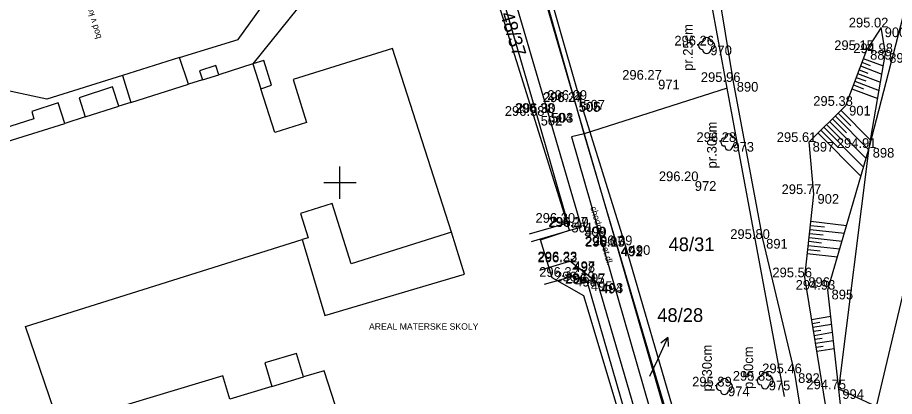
# Model space of a CAD drawing. Extents: x -599970 to -599524, y -1154772 to -1154457.
# Drawn here: x -599820 to -599765.7, y -1154663.2 to -1154639.8 of the extents above; entities that cross this region are included whole.
import ezdxf

# ---------------------------------------------------------------- set-up
doc = ezdxf.new("R2010")
doc.units = 0
for name, color, linetype in [('Z-KATASTRALNI MAPA', 7, 'Continuous'), ('Z-KRIZKY CTVERCOVE SITE', 7, 'Continuous'), ('Z-PLOT DRATENY', 7, 'Continuous'), ('Z-PLOT DREVENY', 7, 'Continuous'), ('Z-PODROBNE BODY', 7, 'Continuous'), ('Z-PODROBNE BODY-CISLO', 7, 'Continuous'), ('Z-PODROBNE BODY-VYSKA', 7, 'Continuous'), ('Z-POPISY OBJEKTU A ZPEVNENYCH PLOCH', 7, 'Continuous'), ('Z-PRUMERY KMENU STROMU', 7, 'Continuous'), ('Z-SRAFOVANI SVAHU', 7, 'Continuous'), ('Z-STROMY ZNACKY KULTUR', 7, 'Continuous'), ('Z-TERENNI HRANY PATY', 7, 'Continuous'), ('Z-ZPEVNENE PLOCHY', 7, 'Continuous')]:
    doc.layers.add(name, color=color, linetype=linetype)

msp = doc.modelspace()

# ---------------------------------------------------------------- linework, layer by layer
at = {"layer": 'Z-KATASTRALNI MAPA'}
for p, q in [((-599776.02, -1154644.14), (-599779.98, -1154622.34)), ((-599809.93, -1154642.24), (-599813.46, -1154643.34)), ((-599805.39, -1154642.63), (-599804.9, -1154644.17)), ((-599808.52, -1154643.62), (-599807.5, -1154643.3)), ((-599812.94, -1154645.02), (-599809.38, -1154643.89)), ((-599776.02, -1154644.14), (-599784.88, -1154646.97)), ((-599772.47, -1154663.26), (-599776.02, -1154644.14)), ((-599815.77, -1154645.92), (-599813.7, -1154645.26)), ((-599818.69, -1154646.84), (-599817.04, -1154646.32)), ((-599823.51, -1154648.36), (-599818.69, -1154646.84)), ((-599779.5, -1154665.17), (-599784.88, -1154646.97)), ((-599800.49, -1154651.29), (-599802.44, -1154651.91)), ((-599799.3, -1154655.03), (-599800.49, -1154651.29)), ((-599802.44, -1154651.91), (-599801.96, -1154653.41)), ((-599801.96, -1154653.41), (-599802.33, -1154653.52)), ((-599793.1, -1154653.06), (-599799.3, -1154655.03)), ((-599780.32, -1154660.95), (-599779.686, -1154659.59)), ((-599779.686, -1154659.59), (-599780.125, -1154659.938)), ((-599779.686, -1154659.59), (-599779.671, -1154660.15)), ((-599780.81, -1154661.98), (-599780.32, -1154660.95)), ((-599804.21, -1154662.63), (-599802.26, -1154662.04))]:
    msp.add_line(p, q, dxfattribs=at)
for points in [[(-599809.93, -1154642.24), (-599806.3, -1154641.11), (-599799.75, -1154632.01), (-599790.77, -1154629.45)], [(-599784.88, -1154646.97), (-599789.9, -1154629.2), (-599790.77, -1154629.45)], [(-599779.65, -1154674.5), (-599784.9, -1154657), (-599786.85, -1154655.89), (-599787.57, -1154653.53), (-599785.79, -1154652.94), (-599792.35, -1154631.92), (-599798.2, -1154633.66), (-599805.39, -1154642.63)], [(-599796.58, -1154675.26), (-599800.97, -1154661.65), (-599802.26, -1154662.04), (-599802.7, -1154660.58), (-599804.66, -1154661.17), (-599804.21, -1154662.63), (-599806.82, -1154663.42), (-599807.26, -1154661.96), (-599817.38, -1154665.03), (-599819.48, -1154658.91), (-599802.33, -1154653.52), (-599800.94, -1154658.22), (-599792.28, -1154655.66), (-599793.1, -1154653.06), (-599796.74, -1154641.67), (-599802.89, -1154643.6), (-599802.08, -1154646.27), (-599804.04, -1154646.89), (-599804.9, -1154644.17), (-599804.23, -1154643.95), (-599804.72, -1154642.42), (-599805.39, -1154642.63)], [(-599813.46, -1154643.34), (-599818.16, -1154644.81), (-599830.56, -1154642.16), (-599867.14, -1154654.18)], [(-599805.39, -1154642.63), (-599807.5, -1154643.3), (-599807.69, -1154642.73), (-599808.7, -1154643.07), (-599808.52, -1154643.62), (-599809.38, -1154643.89), (-599809.93, -1154642.24)], [(-599813.46, -1154643.34), (-599812.94, -1154645.02), (-599813.7, -1154645.26), (-599814.09, -1154644.05), (-599816.15, -1154644.74), (-599815.77, -1154645.92), (-599817.04, -1154646.32), (-599817.45, -1154645.05), (-599819.09, -1154645.58), (-599818.95, -1154646.04), (-599823.76, -1154647.57)], [(-599784.88, -1154646.97), (-599785.65, -1154647.16), (-599780.39, -1154665.46)]]:
    msp.add_lwpolyline(points, dxfattribs=at)
at = {"layer": 'Z-KRIZKY CTVERCOVE SITE'}
for p, q in [((-599800, -1154651), (-599800, -1154649)), ((-599799, -1154650), (-599801, -1154650))]:
    msp.add_line(p, q, dxfattribs=at)
at = {"layer": 'Z-PLOT DRATENY'}
msp.add_line((-599788.27, -1154653.16), (-599785.89, -1154652.48), dxfattribs=at)
for points in [[(-599780.14, -1154619.26), (-599779.06, -1154624.05), (-599777.14, -1154634.68), (-599775.65, -1154643.75), (-599773.83, -1154653.48), (-599771.85, -1154661.81), (-599770.19, -1154672.08)], [(-599790.59, -1154625.68), (-599789.41, -1154629.89), (-599785.15, -1154644.86), (-599782.34, -1154653.87), (-599779.13, -1154664.86), (-599776.51, -1154673.7), (-599770.19, -1154672.08), (-599762.65, -1154670.15), (-599753.18, -1154667.49), (-599743.82, -1154665.08), (-599731.66, -1154661.71), (-599725.96, -1154660.31)], [(-599785.89, -1154652.48), (-599787.79, -1154645.85), (-599792.06, -1154631.16), (-599798.51, -1154633.1)]]:
    msp.add_lwpolyline(points, dxfattribs=at)
at = {"layer": 'Z-PLOT DREVENY'}
msp.add_lwpolyline([(-599779.22, -1154674.68), (-599781.82, -1154666.03), (-599784.68, -1154656.11), (-599785.66, -1154655.83), (-599787.35, -1154656.31)], dxfattribs=at)
at = {"layer": 'Z-PODROBNE BODY'}
for p, q in [((-599766.49, -1154640.37), (-599766.49, -1154640.37)), ((-599777.29, -1154641.49), (-599777.29, -1154641.49)), ((-599767.39, -1154641.77), (-599767.39, -1154641.77)), ((-599766.21, -1154641.96), (-599766.21, -1154641.96)), ((-599780.52, -1154643.61), (-599780.52, -1154643.61)), ((-599775.65, -1154643.75), (-599775.65, -1154643.75)), ((-599785.44, -1154645), (-599785.44, -1154645)), ((-599785.41, -1154644.98), (-599785.41, -1154644.98)), ((-599785.15, -1154644.86), (-599785.15, -1154644.86)), ((-599768.69, -1154645.23), (-599768.69, -1154645.23)), ((-599787.79, -1154645.85), (-599787.79, -1154645.85)), ((-599787.17, -1154645.67), (-599787.17, -1154645.67)), ((-599787.11, -1154645.67), (-599787.11, -1154645.67)), ((-599775.92, -1154647.47), (-599775.92, -1154647.47)), ((-599770.95, -1154647.47), (-599770.95, -1154647.47)), ((-599767.23, -1154647.84), (-599767.23, -1154647.84)), ((-599778.25, -1154649.9), (-599778.25, -1154649.9)), ((-599770.65, -1154650.7), (-599770.65, -1154650.7)), ((-599785.89, -1154652.48), (-599785.89, -1154652.48)), ((-599785.1, -1154652.72), (-599785.1, -1154652.72)), ((-599785.05, -1154652.74), (-599785.05, -1154652.74)), ((-599773.83, -1154653.48), (-599773.83, -1154653.48)), ((-599782.84, -1154653.93), (-599782.84, -1154653.93)), ((-599782.81, -1154653.96), (-599782.81, -1154653.96)), ((-599782.34, -1154653.87), (-599782.34, -1154653.87)), ((-599785.76, -1154654.87), (-599785.76, -1154654.87)), ((-599785.76, -1154654.93), (-599785.76, -1154654.93)), ((-599785.66, -1154655.83), (-599785.66, -1154655.83)), ((-599784.68, -1154656.11), (-599784.68, -1154656.11)), ((-599784.06, -1154656.26), (-599784.06, -1154656.26)), ((-599784.02, -1154656.22), (-599784.02, -1154656.22)), ((-599771.22, -1154655.86), (-599771.22, -1154655.86)), ((-599769.78, -1154656.63), (-599769.78, -1154656.63)), ((-599771.85, -1154661.81), (-599771.85, -1154661.81)), ((-599776.19, -1154662.63), (-599776.19, -1154662.63)), ((-599773.67, -1154662.27), (-599773.67, -1154662.27)), ((-599769.11, -1154662.8), (-599769.11, -1154662.8))]:
    msp.add_line(p, q, dxfattribs=at)
at = {"layer": 'Z-SRAFOVANI SVAHU'}
for points in [[(-599767.68, -1154642.53), (-599767.16, -1154642.72)], [(-599767.59, -1154642.3), (-599766.35, -1154642.76)], [(-599767.85, -1154643), (-599767.3, -1154643.2)], [(-599767.76, -1154642.76), (-599766.44, -1154643.26)], [(-599768.12, -1154643.7), (-599766.61, -1154644.27)], [(-599768.03, -1154643.47), (-599767.44, -1154643.69)], [(-599767.94, -1154643.23), (-599766.52, -1154643.76)], [(-599768.29, -1154644.17), (-599766.7, -1154644.77)], [(-599768.2, -1154643.93), (-599767.58, -1154644.17)], [(-599769.33, -1154645.86), (-599767.26, -1154647.94)], [(-599769.15, -1154645.68), (-599768.37, -1154646.47)], [(-599768.97, -1154645.51), (-599767.15, -1154647.35)], [(-599769.86, -1154646.39), (-599768.91, -1154647.34)], [(-599769.68, -1154646.21), (-599767.42, -1154648.49)], [(-599769.5, -1154646.04), (-599768.64, -1154646.91)], [(-599770.39, -1154646.92), (-599767.74, -1154649.59)], [(-599770.21, -1154646.74), (-599769.19, -1154647.77)], [(-599770.04, -1154646.56), (-599767.58, -1154649.04)], [(-599770.84, -1154652.39), (-599768.62, -1154652.64)], [(-599770.89, -1154652.89), (-599768.76, -1154653.12)], [(-599770.86, -1154652.64), (-599770, -1154652.74)], [(-599770.95, -1154653.39), (-599768.9, -1154653.61)], [(-599770.92, -1154653.14), (-599770.08, -1154653.23)], [(-599771, -1154653.88), (-599769.05, -1154654.1)], [(-599770.97, -1154653.63), (-599770.17, -1154653.72)], [(-599771.06, -1154654.38), (-599769.19, -1154654.59)], [(-599771.03, -1154654.13), (-599770.26, -1154654.22)], [(-599770.79, -1154658.47), (-599769.6, -1154658.28)], [(-599770.75, -1154658.72), (-599770.28, -1154658.64)], [(-599770.71, -1154658.96), (-599769.55, -1154658.77)], [(-599770.67, -1154659.21), (-599770.21, -1154659.14)], [(-599770.63, -1154659.46), (-599769.49, -1154659.27)], [(-599770.59, -1154659.7), (-599770.14, -1154659.63)], [(-599770.55, -1154659.95), (-599769.44, -1154659.77)], [(-599770.51, -1154660.2), (-599770.07, -1154660.13)], [(-599770.47, -1154660.44), (-599769.39, -1154660.27)]]:
    msp.add_lwpolyline(points, dxfattribs=at)
at = {"layer": 'Z-STROMY ZNACKY KULTUR'}
for centre in [(-599777.29, -1154641.49), (-599775.92, -1154647.47), (-599776.19, -1154662.63), (-599773.67, -1154662.27)]:
    msp.add_circle(centre, 0.00025, dxfattribs=at)
for centre, start, end in [((-599777.29, -1154641.24), 0, 180), ((-599777.54, -1154641.49), 90, 270), ((-599777.04, -1154641.49), 270, 90), ((-599777.29, -1154641.74), 180, 360), ((-599775.92, -1154647.22), 0, 180), ((-599776.17, -1154647.47), 90, 270), ((-599775.67, -1154647.47), 270, 90), ((-599775.92, -1154647.72), 180, 360), ((-599776.19, -1154662.38), 0, 180), ((-599773.92, -1154662.27), 90, 270), ((-599773.67, -1154662.02), 0, 180), ((-599773.42, -1154662.27), 270, 90), ((-599776.44, -1154662.63), 90, 270), ((-599775.94, -1154662.63), 270, 90), ((-599773.67, -1154662.52), 180, 360), ((-599776.19, -1154662.88), 180, 360)]:
    msp.add_arc(centre, 0.25, start, end, dxfattribs=at)
at = {"layer": 'Z-TERENNI HRANY PATY'}
for points in [[(-599770.19, -1154672.08), (-599768.8, -1154665.69), (-599769.11, -1154662.8), (-599769.78, -1154656.63), (-599767.23, -1154647.84), (-599766.21, -1154641.96), (-599766.49, -1154640.37)], [(-599766.49, -1154640.37), (-599767.39, -1154641.77), (-599768.69, -1154645.23)], [(-599770.19, -1154672.08), (-599769.91, -1154663.87), (-599771.22, -1154655.86), (-599770.65, -1154650.7), (-599770.95, -1154647.47), (-599768.69, -1154645.23)]]:
    msp.add_lwpolyline(points, dxfattribs=at)
at = {"layer": 'Z-ZPEVNENE PLOCHY'}
for p, q in [((-599788.13, -1154653.64), (-599785.05, -1154652.74)), ((-599787.62, -1154655.41), (-599785.76, -1154654.87))]:
    msp.add_line(p, q, dxfattribs=at)
for points in [[(-599754.14, -1154621.91), (-599757.46, -1154625.05), (-599757.52, -1154625.29), (-599760.31, -1154636.94), (-599763.2, -1154648.7), (-599766.8, -1154663.87), (-599769.11, -1154662.8), (-599767.23, -1154647.84), (-599764.82, -1154638.47), (-599762.25, -1154627.96), (-599761.65, -1154625.43)], [(-599776.8, -1154674.93), (-599776.98, -1154673.98), (-599779.61, -1154665.08), (-599782.84, -1154653.93), (-599785.44, -1154645), (-599789.78, -1154630.07), (-599790.16, -1154628.81)], [(-599785.05, -1154652.74), (-599787.11, -1154645.67), (-599791.52, -1154630.59), (-599798.8, -1154632.75)], [(-599778.47, -1154675.47), (-599778.71, -1154674.46), (-599781.23, -1154665.86), (-599784.02, -1154656.22), (-599785.76, -1154654.87)]]:
    msp.add_lwpolyline(points, dxfattribs=at)

# ---------------------------------------------------------------- texts
at = {"layer": 'Z-KATASTRALNI MAPA'}
msp.add_text('48/37', height=0.85, rotation=287, dxfattribs=at).set_placement((-599790.083, -1154639.543))
for s, p in [('48/31', (-599779.649, -1154654.24)), ('48/28', (-599780.35, -1154658.63))]:
    msp.add_text(s, height=0.85, dxfattribs=at).set_placement(p)
at = {"layer": 'Z-PODROBNE BODY-CISLO'}
for s, p in [(' 900', (-599766.49, -1154640.97)), (' 970', (-599777.29, -1154642.09)), (' 889', (-599767.39, -1154642.37)), (' 899', (-599766.21, -1154642.56)), (' 971', (-599780.52, -1154644.21)), (' 890', (-599775.65, -1154644.35)), (' 507', (-599785.15, -1154645.46)), (' 505', (-599785.44, -1154645.6)), (' 506', (-599785.41, -1154645.58)), (' 901', (-599768.69, -1154645.83)), (' 502', (-599787.79, -1154646.45)), (' 504', (-599787.17, -1154646.27)), (' 503', (-599787.11, -1154646.27)), (' 973', (-599775.92, -1154648.07)), (' 897', (-599770.95, -1154648.07)), (' 898', (-599767.23, -1154648.44)), (' 972', (-599778.25, -1154650.5)), (' 902', (-599770.65, -1154651.3)), (' 501', (-599785.89, -1154653.08)), (' 500', (-599785.1, -1154653.32)), (' 499', (-599785.05, -1154653.34)), (' 891', (-599773.83, -1154654.08)), (' 491', (-599782.84, -1154654.53)), (' 492', (-599782.81, -1154654.56)), (' 490', (-599782.34, -1154654.47)), (' 497', (-599785.76, -1154655.47)), (' 498', (-599785.76, -1154655.53)), (' 496', (-599785.66, -1154656.43)), (' 495', (-599784.68, -1154656.71)), (' 494', (-599784.06, -1154656.86)), (' 493', (-599784.02, -1154656.82)), (' 896', (-599771.22, -1154656.46)), (' 895', (-599769.78, -1154657.23)), (' 892', (-599771.85, -1154662.41)), (' 974', (-599776.19, -1154663.23)), (' 975', (-599773.67, -1154662.87)), (' 994', (-599769.11, -1154663.4))]:
    msp.add_text(s, height=0.6, dxfattribs=at).set_placement(p)
at = {"layer": 'Z-PODROBNE BODY-VYSKA'}
for s, p in [('295.02 ', (-599768.49, -1154640.37)), ('296.26 ', (-599779.29, -1154641.49)), ('295.15 ', (-599769.39, -1154641.77)), ('294.98 ', (-599768.21, -1154641.96)), ('296.27 ', (-599782.52, -1154643.61)), ('295.96 ', (-599777.65, -1154643.75)), ('296.29 ', (-599787.15, -1154644.86)), ('296.27 ', (-599787.44, -1154645)), ('296.34 ', (-599787.41, -1154644.98)), ('295.38 ', (-599770.69, -1154645.23)), ('296.38 ', (-599789.79, -1154645.85)), ('296.38 ', (-599789.17, -1154645.67)), ('296.30 ', (-599789.11, -1154645.67)), ('296.28 ', (-599777.92, -1154647.47)), ('295.61 ', (-599772.95, -1154647.47)), ('294.91 ', (-599769.23, -1154647.84)), ('296.20 ', (-599780.25, -1154649.9)), ('295.77 ', (-599772.65, -1154650.7)), ('296.30 ', (-599787.89, -1154652.48)), ('296.27 ', (-599787.1, -1154652.72)), ('296.19 ', (-599787.05, -1154652.74)), ('295.80 ', (-599775.83, -1154653.48)), ('296.07 ', (-599784.84, -1154653.93)), ('296.15 ', (-599784.81, -1154653.96)), ('296.09 ', (-599784.34, -1154653.87)), ('296.23 ', (-599787.76, -1154654.87)), ('296.32 ', (-599787.76, -1154654.93)), ('296.32 ', (-599787.66, -1154655.83)), ('296.19 ', (-599786.68, -1154656.11)), ('296.15 ', (-599786.06, -1154656.26)), ('296.07 ', (-599786.02, -1154656.22)), ('295.56 ', (-599773.22, -1154655.86)), ('294.93 ', (-599771.78, -1154656.63)), ('295.85 ', (-599775.67, -1154662.27)), ('295.46 ', (-599773.85, -1154661.81)), ('295.89 ', (-599778.19, -1154662.63)), ('294.75 ', (-599771.11, -1154662.8))]:
    msp.add_text(s, height=0.6, dxfattribs=at).set_placement(p)
at = {"layer": 'Z-POPISY OBJEKTU A ZPEVNENYCH PLOCH'}
for s, rotation, p in [('bod v komunikaci', 106.301, (-599814.76, -1154641.01)), ('chodnik - bet.dl.', 286.2446, (-599784.5, -1154651.53))]:
    msp.add_text(s, height=0.4, rotation=rotation, dxfattribs=at).set_placement(p)
msp.add_text('AREAL MATERSKE SKOLY', height=0.4, dxfattribs=at).set_placement((-599798.2, -1154659.11))
at = {"layer": 'Z-PRUMERY KMENU STROMU'}
for s, p in [('pr.25cm', (-599778.15, -1154643.06)), ('pr.30cm', (-599776.67, -1154649.11)), ('pr.30cm', (-599776.97, -1154662.94)), ('p.50cm', (-599774.41, -1154662.78))]:
    msp.add_text(s, height=0.6, rotation=90, dxfattribs=at).set_placement(p)

doc.saveas('drawing.dxf')
